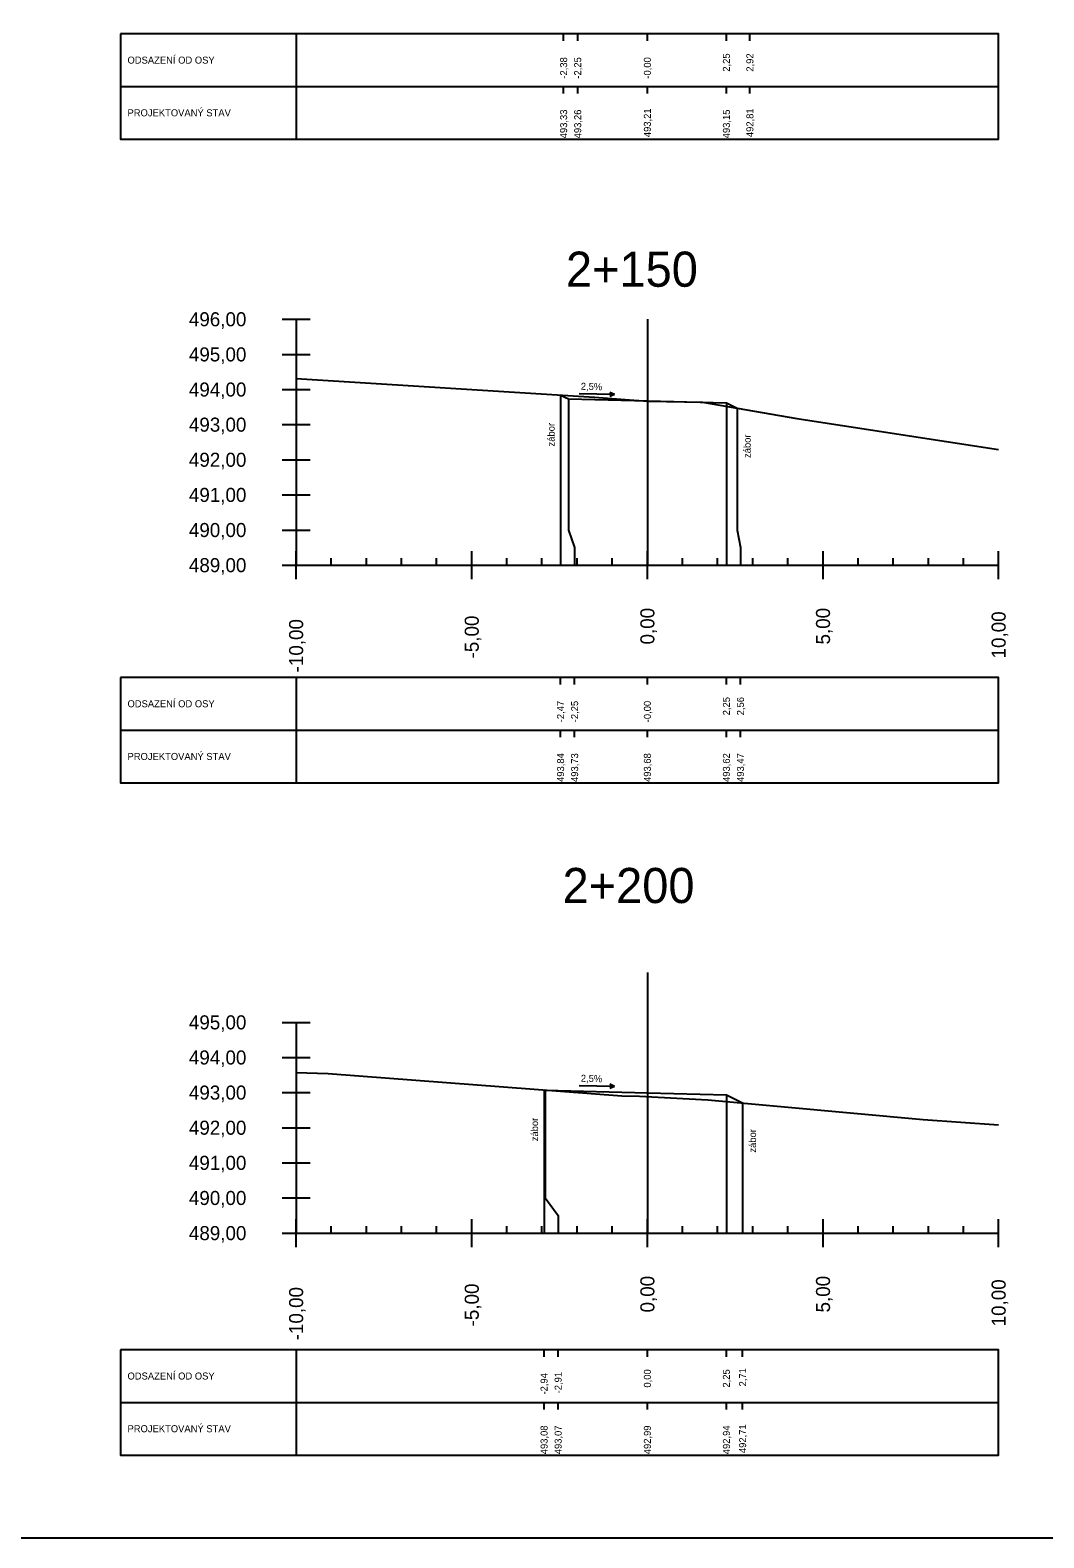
# Model space of a CAD drawing. Extents: x -631407 to -631215, y -1089700 to -1088598.
# Drawn here: x -631287.77 to -631258.91, y -1088943.43 to -1088900.51 of the extents above; entities that cross this region are included whole.
import ezdxf

# ---------------------------------------------------------------- set-up
doc = ezdxf.new("R2010")
doc.units = 0
for name, color, linetype in [('08_LEGENDA_HV', 7, 'Continuous'), ('59', 7, 'Continuous'), ('NIVELETA_VYSKY', 7, 'Continuous'), ('REZ_BODY', 7, 'Continuous'), ('REZ_ODSTUPY', 7, 'Continuous'), ('REZ_POPIS', 7, 'Continuous'), ('REZ_RAMY', 7, 'Continuous'), ('REZ_STANICENI', 7, 'Continuous'), ('REZ_SVISLE', 7, 'Continuous'), ('REZ_TENKA', 7, 'Continuous'), ('REZ_TLUSTA', 7, 'Continuous'), ('TABULKA_POPIS', 7, 'Continuous'), ('TEREN', 7, 'Continuous'), ('zábor', 7, 'Continuous')]:
    doc.layers.add(name, color=color, linetype=linetype)

msp = doc.modelspace()

# ---------------------------------------------------------------- linework, layer by layer
at = {"layer": '08_LEGENDA_HV'}
msp.add_lwpolyline([(-631215.384, -1088943.435), (-631215.384, -1088765.235), (-631407.014, -1088765.235), (-631407.014, -1088943.435)], close=True, dxfattribs=at)
at = {"layer": '59'}
for p, q in [((-631280.602, -1088908.743), (-631279.802, -1088908.743)), ((-631280.202, -1088908.743), (-631280.202, -1088915.743)), ((-631280.602, -1088909.743), (-631279.802, -1088909.743)), ((-631280.602, -1088910.743), (-631279.802, -1088910.743)), ((-631280.602, -1088911.743), (-631279.802, -1088911.743)), ((-631280.602, -1088912.743), (-631279.802, -1088912.743)), ((-631280.602, -1088913.743), (-631279.802, -1088913.743)), ((-631280.602, -1088914.743), (-631279.802, -1088914.743)), ((-631280.602, -1088915.743), (-631279.802, -1088915.743)), ((-631280.602, -1088928.759), (-631279.802, -1088928.759)), ((-631280.202, -1088928.759), (-631280.202, -1088934.759)), ((-631280.602, -1088929.759), (-631279.802, -1088929.759)), ((-631280.602, -1088930.759), (-631279.802, -1088930.759)), ((-631280.602, -1088931.759), (-631279.802, -1088931.759)), ((-631280.602, -1088932.759), (-631279.802, -1088932.759)), ((-631280.602, -1088933.759), (-631279.802, -1088933.759)), ((-631280.602, -1088934.759), (-631279.802, -1088934.759))]:
    msp.add_line(p, q, dxfattribs=at)
at = {"layer": 'REZ_RAMY'}
for p, q in [((-631285.202, -1088900.615), (-631285.202, -1088903.615)), ((-631280.202, -1088900.615), (-631280.202, -1088903.615)), ((-631272.586, -1088900.815), (-631272.586, -1088900.615)), ((-631272.186, -1088900.815), (-631272.186, -1088900.615)), ((-631270.202, -1088900.815), (-631270.202, -1088900.615)), ((-631267.952, -1088900.815), (-631267.952, -1088900.615)), ((-631267.283, -1088900.815), (-631267.283, -1088900.615)), ((-631285.202, -1088902.115), (-631260.202, -1088902.115)), ((-631272.586, -1088902.315), (-631272.586, -1088902.115)), ((-631272.186, -1088902.315), (-631272.186, -1088902.115)), ((-631270.202, -1088902.315), (-631270.202, -1088902.115)), ((-631267.952, -1088902.315), (-631267.952, -1088902.115)), ((-631267.283, -1088902.315), (-631267.283, -1088902.115)), ((-631285.202, -1088918.939), (-631285.202, -1088921.939)), ((-631280.202, -1088918.939), (-631280.202, -1088921.939)), ((-631272.673, -1088919.139), (-631272.673, -1088918.939)), ((-631272.273, -1088919.139), (-631272.273, -1088918.939)), ((-631270.202, -1088919.139), (-631270.202, -1088918.939)), ((-631267.952, -1088919.139), (-631267.952, -1088918.939)), ((-631267.552, -1088919.139), (-631267.552, -1088918.939)), ((-631285.202, -1088920.439), (-631260.202, -1088920.439)), ((-631272.673, -1088920.639), (-631272.673, -1088920.439)), ((-631272.273, -1088920.639), (-631272.273, -1088920.439)), ((-631270.202, -1088920.639), (-631270.202, -1088920.439)), ((-631267.952, -1088920.639), (-631267.952, -1088920.439)), ((-631267.552, -1088920.639), (-631267.552, -1088920.439)), ((-631285.202, -1088938.078), (-631285.202, -1088941.078)), ((-631280.202, -1088938.078), (-631280.202, -1088941.078)), ((-631273.143, -1088938.278), (-631273.143, -1088938.078)), ((-631272.743, -1088938.278), (-631272.743, -1088938.078)), ((-631270.202, -1088938.278), (-631270.202, -1088938.078)), ((-631267.952, -1088938.278), (-631267.952, -1088938.078)), ((-631267.49, -1088938.278), (-631267.49, -1088938.078)), ((-631285.202, -1088939.578), (-631260.202, -1088939.578)), ((-631273.143, -1088939.778), (-631273.143, -1088939.578)), ((-631272.743, -1088939.778), (-631272.743, -1088939.578)), ((-631270.202, -1088939.778), (-631270.202, -1088939.578)), ((-631267.952, -1088939.778), (-631267.952, -1088939.578)), ((-631267.49, -1088939.778), (-631267.49, -1088939.578))]:
    msp.add_line(p, q, dxfattribs=at)
for points in [[(-631285.202, -1088900.615), (-631285.202, -1088903.615), (-631260.202, -1088903.615), (-631260.202, -1088900.615)], [(-631285.202, -1088918.939), (-631285.202, -1088921.939), (-631260.202, -1088921.939), (-631260.202, -1088918.939)], [(-631285.202, -1088938.078), (-631285.202, -1088941.078), (-631260.202, -1088941.078), (-631260.202, -1088938.078)]]:
    msp.add_lwpolyline(points, close=True, dxfattribs=at)
at = {"layer": 'REZ_SVISLE'}
for points in [[(-631272.673, -1088910.9), (-631272.673, -1088914.743), (-631272.673, -1088915.243), (-631272.673, -1088915.743)], [(-631272.452, -1088911.011), (-631272.452, -1088914.743), (-631272.273, -1088915.243), (-631272.273, -1088915.743)], [(-631270.202, -1088911.067), (-631270.202, -1088914.743), (-631270.202, -1088915.243), (-631270.202, -1088915.743)], [(-631267.952, -1088911.123), (-631267.952, -1088914.743), (-631267.952, -1088915.243), (-631267.952, -1088915.743)], [(-631267.643, -1088911.277), (-631267.643, -1088914.743), (-631267.552, -1088915.243), (-631267.552, -1088915.743)], [(-631273.143, -1088930.681), (-631273.143, -1088933.759), (-631273.143, -1088934.259), (-631273.143, -1088934.759)], [(-631273.116, -1088930.694), (-631273.116, -1088933.759), (-631272.743, -1088934.259), (-631272.743, -1088934.759)], [(-631270.202, -1088930.767), (-631270.202, -1088933.759), (-631270.202, -1088934.259), (-631270.202, -1088934.759)], [(-631267.952, -1088930.823), (-631267.952, -1088933.759), (-631267.952, -1088934.259), (-631267.952, -1088934.759)], [(-631267.49, -1088931.054), (-631267.49, -1088933.759), (-631267.49, -1088934.259), (-631267.49, -1088934.759)]]:
    msp.add_lwpolyline(points, dxfattribs=at)
at = {"layer": 'REZ_TENKA'}
for p, q in [((-631279.202, -1088915.743), (-631279.202, -1088915.543)), ((-631278.202, -1088915.743), (-631278.202, -1088915.543)), ((-631277.202, -1088915.743), (-631277.202, -1088915.543)), ((-631276.202, -1088915.743), (-631276.202, -1088915.543)), ((-631274.202, -1088915.743), (-631274.202, -1088915.543)), ((-631273.202, -1088915.743), (-631273.202, -1088915.543)), ((-631272.202, -1088915.743), (-631272.202, -1088915.543)), ((-631271.202, -1088915.743), (-631271.202, -1088915.543)), ((-631269.202, -1088915.743), (-631269.202, -1088915.543)), ((-631268.202, -1088915.743), (-631268.202, -1088915.543)), ((-631267.202, -1088915.743), (-631267.202, -1088915.543)), ((-631266.202, -1088915.743), (-631266.202, -1088915.543)), ((-631264.202, -1088915.743), (-631264.202, -1088915.543)), ((-631263.202, -1088915.743), (-631263.202, -1088915.543)), ((-631262.202, -1088915.743), (-631262.202, -1088915.543)), ((-631261.202, -1088915.743), (-631261.202, -1088915.543)), ((-631279.202, -1088934.759), (-631279.202, -1088934.559)), ((-631278.202, -1088934.759), (-631278.202, -1088934.559)), ((-631277.202, -1088934.759), (-631277.202, -1088934.559)), ((-631276.202, -1088934.759), (-631276.202, -1088934.559)), ((-631274.202, -1088934.759), (-631274.202, -1088934.559)), ((-631273.202, -1088934.759), (-631273.202, -1088934.559)), ((-631272.202, -1088934.759), (-631272.202, -1088934.559)), ((-631271.202, -1088934.759), (-631271.202, -1088934.559)), ((-631269.202, -1088934.759), (-631269.202, -1088934.559)), ((-631268.202, -1088934.759), (-631268.202, -1088934.559)), ((-631267.202, -1088934.759), (-631267.202, -1088934.559)), ((-631266.202, -1088934.759), (-631266.202, -1088934.559)), ((-631264.202, -1088934.759), (-631264.202, -1088934.559)), ((-631263.202, -1088934.759), (-631263.202, -1088934.559)), ((-631262.202, -1088934.759), (-631262.202, -1088934.559)), ((-631261.202, -1088934.759), (-631261.202, -1088934.559))]:
    msp.add_line(p, q, dxfattribs=at)
at = {"layer": 'REZ_TLUSTA'}
for p, q in [((-631270.202, -1088908.743), (-631270.202, -1088915.743)), ((-631280.202, -1088916.143), (-631280.202, -1088915.343)), ((-631275.202, -1088916.143), (-631275.202, -1088915.343)), ((-631270.202, -1088916.143), (-631270.202, -1088915.343)), ((-631265.202, -1088916.143), (-631265.202, -1088915.343)), ((-631260.202, -1088916.143), (-631260.202, -1088915.343)), ((-631280.202, -1088915.743), (-631260.202, -1088915.743)), ((-631270.202, -1088927.339), (-631270.202, -1088934.759)), ((-631280.202, -1088935.159), (-631280.202, -1088934.359)), ((-631275.202, -1088935.159), (-631275.202, -1088934.359)), ((-631270.202, -1088935.159), (-631270.202, -1088934.359)), ((-631265.202, -1088935.159), (-631265.202, -1088934.359)), ((-631260.202, -1088935.159), (-631260.202, -1088934.359)), ((-631280.202, -1088934.759), (-631260.202, -1088934.759))]:
    msp.add_line(p, q, dxfattribs=at)
at = {"layer": 'TEREN'}
for points in [[(-631280.202, -1088910.432), (-631271.71, -1088910.96), (-631270.591, -1088911.047), (-631270.168, -1088911.077), (-631268.636, -1088911.106), (-631265.945, -1088911.572), (-631260.202, -1088912.449)], [(-631272.673, -1088910.9), (-631272.452, -1088911.011), (-631270.202, -1088911.067), (-631267.952, -1088911.123), (-631267.643, -1088911.277)], [(-631280.202, -1088930.19), (-631279.286, -1088930.218), (-631270.932, -1088930.847), (-631270.429, -1088930.856), (-631268.477, -1088930.963), (-631262.354, -1088931.526), (-631260.202, -1088931.674)], [(-631273.143, -1088930.681), (-631273.116, -1088930.694), (-631270.202, -1088930.767), (-631267.952, -1088930.823), (-631267.49, -1088931.054)]]:
    msp.add_lwpolyline(points, dxfattribs=at)
at = {"layer": 'zábor'}
for p, q in [((-631271.135, -1088910.887), (-631272.143, -1088910.862)), ((-631271.135, -1088910.887), (-631271.274, -1088910.945)), ((-631271.135, -1088910.887), (-631271.271, -1088910.823)), ((-631271.135, -1088930.587), (-631272.143, -1088930.562)), ((-631271.135, -1088930.587), (-631271.274, -1088930.645)), ((-631271.135, -1088930.587), (-631271.271, -1088930.523))]:
    msp.add_line(p, q, dxfattribs=at)

# ---------------------------------------------------------------- texts
at = {"layer": 'NIVELETA_VYSKY'}
for s, p in [('493,33', (-631272.486, -1088903.591)), ('493,26', (-631272.086, -1088903.591)), ('493,21', (-631270.102, -1088903.557)), ('493,15', (-631267.852, -1088903.591)), ('492,81', (-631267.183, -1088903.557)), ('493,84', (-631272.573, -1088921.915)), ('493,73', (-631272.173, -1088921.915)), ('493,68', (-631270.102, -1088921.915)), ('493,62', (-631267.852, -1088921.915)), ('493,47', (-631267.452, -1088921.915)), ('493,08', (-631273.043, -1088941.054)), ('493,07', (-631272.643, -1088941.054)), ('492,99', (-631270.102, -1088941.054)), ('492,94', (-631267.852, -1088941.054)), ('492,71', (-631267.39, -1088941.021))]:
    msp.add_text(s, height=0.2, rotation=90, dxfattribs=at).set_placement(p)
at = {"layer": 'REZ_BODY'}
for s, p in [('-2,38', (-631272.486, -1088901.892)), ('-2,25', (-631272.086, -1088901.892)), ('-0,00', (-631270.102, -1088901.892)), ('2,25', (-631267.852, -1088901.694)), ('2,92', (-631267.183, -1088901.694)), ('-2,47', (-631272.573, -1088920.216)), ('-2,25', (-631272.173, -1088920.216)), ('-0,00', (-631270.102, -1088920.216)), ('2,25', (-631267.852, -1088920.018)), ('2,56', (-631267.452, -1088920.018)), ('0,00', (-631270.102, -1088939.157)), ('2,25', (-631267.852, -1088939.157)), ('2,71', (-631267.39, -1088939.124)), ('-2,94', (-631273.043, -1088939.355)), ('-2,91', (-631272.643, -1088939.322))]:
    msp.add_text(s, height=0.2, rotation=90, dxfattribs=at).set_placement(p)
at = {"layer": 'REZ_ODSTUPY'}
for s, p in [('-5,00', (-631275.002, -1088918.398)), ('0,00', (-631270.002, -1088918.001)), ('5,00', (-631265.002, -1088918.001)), ('10,00', (-631260.002, -1088918.398)), ('-10,00', (-631280.002, -1088918.795)), ('0,00', (-631270.002, -1088937.018)), ('5,00', (-631265.002, -1088937.018)), ('10,00', (-631260.002, -1088937.414)), ('-10,00', (-631280.002, -1088937.811)), ('-5,00', (-631275.002, -1088937.414))]:
    msp.add_text(s, height=0.4, rotation=90, dxfattribs=at).set_placement(p)
at = {"layer": 'REZ_POPIS'}
for s, p in [('496,00', (-631283.254, -1088908.943)), ('495,00', (-631283.254, -1088909.943)), ('494,00', (-631283.254, -1088910.943)), ('493,00', (-631283.254, -1088911.943)), ('492,00', (-631283.254, -1088912.943)), ('491,00', (-631283.254, -1088913.943)), ('490,00', (-631283.254, -1088914.943)), ('489,00', (-631283.254, -1088915.943)), ('495,00', (-631283.254, -1088928.959)), ('494,00', (-631283.254, -1088929.959)), ('493,00', (-631283.254, -1088930.959)), ('492,00', (-631283.254, -1088931.959)), ('491,00', (-631283.254, -1088932.959)), ('490,00', (-631283.254, -1088933.959)), ('489,00', (-631283.254, -1088934.959))]:
    msp.add_text(s, height=0.4, dxfattribs=at).set_placement(p)
at = {"layer": 'REZ_STANICENI'}
for s, p in [('2+150', (-631272.52, -1088907.817)), ('2+200', (-631272.616, -1088925.363))]:
    msp.add_text(s, height=1, dxfattribs=at).set_placement(p)
at = {"layer": 'TABULKA_POPIS'}
for s, p in [('ODSAZENÍ OD OSY', (-631285.002, -1088901.465)), ('PROJEKTOVANÝ STAV', (-631285.002, -1088902.965)), ('ODSAZENÍ OD OSY', (-631285.002, -1088919.789)), ('PROJEKTOVANÝ STAV', (-631285.002, -1088921.289)), ('ODSAZENÍ OD OSY', (-631285.002, -1088938.928)), ('PROJEKTOVANÝ STAV', (-631285.002, -1088940.428))]:
    msp.add_text(s, height=0.2, dxfattribs=at).set_placement(p)
at = {"layer": 'zábor'}
for s, rotation, p in [('2,5%', 358.5679, (-631272.099, -1088910.75)), ('zábor', 90, (-631272.843, -1088912.364)), ('zábor', 90, (-631267.261, -1088912.692)), ('2,5%', 358.5679, (-631272.099, -1088930.45)), ('zábor', 90, (-631273.313, -1088932.144)), ('zábor', 90, (-631267.107, -1088932.468))]:
    msp.add_text(s, height=0.2, rotation=rotation, dxfattribs=at).set_placement(p)

doc.saveas('drawing.dxf')
